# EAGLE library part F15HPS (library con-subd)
SUB-D
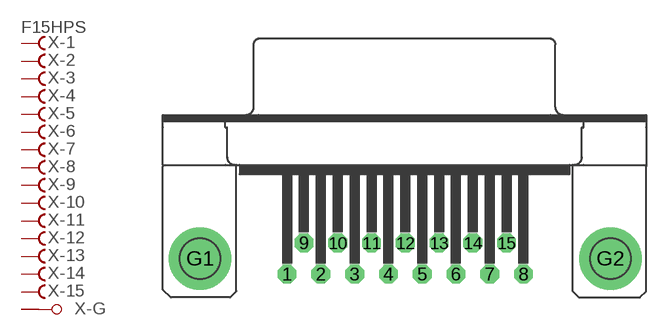
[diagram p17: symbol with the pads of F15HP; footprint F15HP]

Designator prefix X; gates -2=F -3=F -4=F -5=F -6=F -7=F -8=F -9=F -10=F -11=F -12=F -13=F -14=F -15=F -G=GND -1=FV

## F15HPS (OC_FARNELL: unknown; OC_NEWARK: unknown)  [F15HP]
1  -1:F  pas
2  -2:F  pas
3  -3:F  pas
4  -4:F  pas
5  -5:F  pas
6  -6:F  pas
7  -7:F  pas
8  -8:F  pas
9  -9:F  pas
10  -10:F  pas
11  -11:F  pas
12  -12:F  pas
13  -13:F  pas
14  -14:F  pas
15  -15:F  pas
G1  -G:G1  pas
G2  -G:G2  pas

## Footprint F15HP (pad centres in mm)
SUB-D
drill 1.016 octagon: 1 -9.601,-1.27; 2 -6.858,-1.27; 3 -4.115,-1.27; 4 -1.372,-1.27; 5 1.372,-1.27; 6 4.115,-1.27; 7 6.858,-1.27; 8 9.601,-1.27; 9 -8.23,1.27; 10 -5.486,1.27; 11 -2.743,1.27; 12 0,1.27; 13 2.743,1.27; 14 5.486,1.27; 15 8.23,1.27
drill 3.302 pad 5.08 round: G1 -16.662,0; G2 16.662,0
